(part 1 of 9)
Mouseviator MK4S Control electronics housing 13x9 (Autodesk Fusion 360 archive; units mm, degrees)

design "Mouseviator MK4S Control electronics housing 13x9" references "aurdino UNO v5"
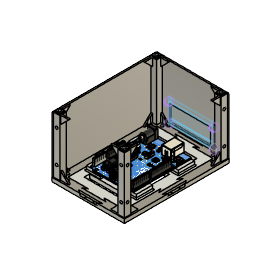
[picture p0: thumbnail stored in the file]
part number: Mouseviator MK4S Control electronics housing 13x9
parameter "plate_width" = 130
parameter "plate_height" = 90
parameter "join_width1" = 10
parameter "join_width2" = 15
parameter "join_depth" = 3
parameter "plate_thick" = 5
parameter "plate_mount_square_side" = 7
parameter "locke_handle_height_1" = 8
parameter "lock_handle_chamfer_1" = 5
parameter "lock_handle_fillet_1" = 0.5
parameter "column_height" = 70
parameter "support_column_side" = 8
parameter "top_cover_thickness" = 3
parameter "wall_clearance" = 0.05
parameter "print_layer_height" = 0.2
parameter "side_wall_thick1" = 0.95 (= "( ( plate_square_thick - support_column_side ) / 2 ) - wall_clearance")
parameter "side_wall_thick2" = 1.95 (= "plate_square_thick - support_column_side - wall_clearance")
parameter "side_wall_length_L_inner" = 111.9 (= "plate_width - ( side_wall_col_length * 2 )")
parameter "side_wall_length_S_inner" = 71.9 (= "plate_height - ( side_wall_col_length * 2 )")
parameter "join_key_d" = 1.5 (= "join_depth / 2")
parameter "join_key_distance" = 5 (= "join_width1 / 2")
parameter "locke_handle_height_2" = 8
parameter "lock_handle_chamfer_2" = 5
parameter "lock_handle_fillet_2" = 0.5
parameter "locke_handle_height_3" = 8
parameter "lock_handle_chamfer_3" = 5
parameter "lock_handle_fillet_3" = 0.5
parameter "lock_column_clearance" = 0.075 (= "wall_clearance * 1.5")
parameter "wago_heigh" = 18
parameter "wago_width" = 6
parameter "wago5_width" = 30 (= "5 * wago_width")
parameter "wago_depth" = 8
parameter "wago10_box_width" = 64 (= "( wago5_width * 2 ) + ( 2 * 2.00 mm )")
parameter "wago_box_height" = 12 (= "wago_depth + ( 2 * 2.00 mm )")
parameter "wago5_box_width" = 34 (= "( wago_width * 5 ) + ( 2 * 2.00 mm )")
parameter "wago3_box_width" = 22.6 (= "wago_width * 3.1 + ( 2 * 2.00 mm )")
parameter "wago_wall_thick" = 2
parameter "mosfet_board_width" = 32.5
parameter "mosfet_baord_height" = 16.5
parameter "fan_relay_board_width" = 33
parameter "fan_relay_board_height" = 25
parameter "uno_doors_clearance" = 0.1
parameter "uno_doors_thick" = 2
parameter "plate_height_1" = 90
parameter "join_width1_1" = 10
parameter "join_width2_1" = 15
parameter "join_depth_1" = 3
parameter "column_height_1" = 70
parameter "support_column_side_1" = 8
parameter "wall_clearance_1" = 0.05
parameter "side_wall_thick1_1" = 0.95 (= "( ( plate_square_thick_1 - support_column_side_1 ) / 2 ) - wall_clearance_1")
parameter "side_wall_thick2_1" = 1.95 (= "plate_square_thick_1 - support_column_side_1 - wall_clearance_1")
parameter "plate_height_2" = 90
parameter "join_width1_2" = 10
parameter "join_width2_2" = 15
parameter "join_depth_2" = 3
parameter "column_height_2" = 70
parameter "support_column_side_2" = 8
parameter "wall_clearance_2" = 0.05
parameter "side_wall_thick1_2" = 0.95 (= "( ( plate_square_thick_2 - support_column_side_2 ) / 2 ) - wall_clearance_2")
parameter "side_wall_thick2_2" = 1.95 (= "plate_square_thick_2 - support_column_side_2 - wall_clearance_2")
parameter "plate_height_3" = 90
parameter "join_width1_3" = 10
parameter "join_width2_3" = 15
parameter "join_depth_3" = 3
parameter "column_height_3" = 70
parameter "support_column_side_3" = 8
parameter "wall_clearance_3" = 0.05
parameter "side_wall_thick1_3" = 0.95 (= "( ( plate_square_thick_3 - support_column_side_3 ) / 2 ) - wall_clearance_3")
parameter "side_wall_thick2_3" = 1.95 (= "plate_square_thick_3 - support_column_side_3 - wall_clearance_3")
parameter "uno_doors_clearance_1" = 0.1
parameter "uno_doors_thick_1" = 2
parameter "plate_height_4" = 90
parameter "join_width1_4" = 10
parameter "join_width2_4" = 15
parameter "join_depth_4" = 3
parameter "column_height_4" = 70
parameter "support_column_side_4" = 8
parameter "wall_clearance_4" = 0.05
parameter "side_wall_thick1_4" = 0.95 (= "( ( plate_square_thick_4 - support_column_side_4 ) / 2 ) - wall_clearance_4")
parameter "side_wall_thick2_4" = 1.95 (= "plate_square_thick_4 - support_column_side_4 - wall_clearance_4")
parameter "joiner_spacing_1" = -0.05
parameter "joiner_spacing_2" = -0.05
parameter "joiner_spacing_2_1" = -0.05
parameter "joiner_spacing_2_2" = -0.05
parameter "joiner_spacing_3_1" = -0.05
parameter "base_vertical_support_width" = 8
parameter "plate_square_thick_1" = 10
parameter "wall_rorner_angle_4" = 45
parameter "plate_square_thick_2" = 10
parameter "wall_rorner_angle_5" = 45
parameter "plate_square_thick_3" = 10
parameter "wall_rorner_angle_6" = 45
parameter "plate_square_thick_4" = 10
parameter "wall_rorner_angle_7" = 45
sketch "Sketch1" plane through (0, 0, 0) normal (0, 0, 1) x axis (1, 0, 0)
  line L1 (100.9644, 61.9879) -> (10.9644, 61.9879)
  line L2 (100.9644, -68.0121) -> (100.9644, 61.9879)
  line L3 (10.9644, -68.0121) -> (100.9644, -68.0121)
  line L4 (10.9644, 61.9879) -> (10.9644, -68.0121)
  line L5 (55.9644, -84.5025) -> (55.9644, 72)
  line L6 (146.0369, -3.0121) -> (3.7538, -3.0121)
  line L7 (90.9644, 51.9879) -> (20.9644, 51.9879)
  line L8 (90.9644, -58.0121) -> (90.9644, 51.9879)
  line L9 (20.9644, -58.0121) -> (90.9644, -58.0121)
  line L10 (20.9644, 51.9879) -> (20.9644, -58.0121)
  line L11 (20.9644, 61.9879) -> (10.9644, 61.9879)
  line L12 (20.9644, 51.9879) -> (20.9644, 61.9879)
  line L13 (10.9644, 51.9879) -> (20.9644, 51.9879)
  line L14 (10.9644, 61.9879) -> (10.9644, 51.9879)
  line L15 (90.9644, 61.9879) -> (100.9644, 61.9879)
  line L16 (90.9644, 51.9879) -> (90.9644, 61.9879)
  line L17 (100.9644, 51.9879) -> (90.9644, 51.9879)
  line L18 (100.9644, 61.9879) -> (100.9644, 51.9879)
  line L19 (90.9644, -68.0121) -> (100.9644, -68.0121)
  line L20 (90.9644, -58.0121) -> (90.9644, -68.0121)
  line L21 (100.9644, -58.0121) -> (90.9644, -58.0121)
  line L22 (100.9644, -68.0121) -> (100.9644, -58.0121)
  line L23 (20.9644, -68.0121) -> (10.9644, -68.0121)
  line L24 (20.9644, -58.0121) -> (20.9644, -68.0121)
  line L25 (10.9644, -58.0121) -> (20.9644, -58.0121)
  line L26 (10.9644, -68.0121) -> (10.9644, -58.0121)
  line L27 (92.9644, 59.9879) -> (98.9644, 59.9879)
  line L28 (92.9644, 53.9879) -> (92.9644, 59.9879)
  line L29 (98.9644, 53.9879) -> (92.9644, 53.9879)
  line L30 (98.9644, 59.9879) -> (98.9644, 53.9879)
  line L31 (18.9644, -66.0121) -> (12.9644, -66.0121)
  line L32 (18.9644, -60.0121) -> (18.9644, -66.0121)
  line L33 (12.9644, -60.0121) -> (18.9644, -60.0121)
  line L34 (12.9644, -66.0121) -> (12.9644, -60.0121)
  line L35 (18.9644, 59.9879) -> (12.9644, 59.9879)
  line L36 (18.9644, 53.9879) -> (18.9644, 59.9879)
  line L37 (12.9644, 53.9879) -> (18.9644, 53.9879)
  line L38 (12.9644, 59.9879) -> (12.9644, 53.9879)
  line L39 (92.9644, -66.0121) -> (98.9644, -66.0121)
  line L40 (92.9644, -60.0121) -> (92.9644, -66.0121)
  line L41 (98.9644, -60.0121) -> (92.9644, -60.0121)
  line L42 (98.9644, -66.0121) -> (98.9644, -60.0121)
  line L43 (45.9644, 51.9879) -> (55.9644, 51.9879)
  line L44 (65.9644, 51.9879) -> (55.9644, 51.9879)
  line L45 (55.9644, 54.9879) -> (55.9644, 51.9879)
  line L46 (70.9644, 54.9879) -> (55.9644, 54.9879)
  line L47 (40.9644, 54.9879) -> (55.9644, 54.9879)
  line L48 (40.9644, 54.9879) -> (45.9644, 51.9879)
  line L49 (65.9644, 51.9879) -> (70.9644, 54.9879)
  line L50 (111.4916, 56.9879) -> (2, 56.9879)
  line L51 (40.9644, 58.9879) -> (55.9644, 58.9879)
  line L52 (40.9644, 58.9879) -> (45.9644, 61.9879)
  line L53 (45.9644, 61.9879) -> (55.9644, 61.9879)
  line L54 (65.9644, 61.9879) -> (70.9644, 58.9879)
  line L55 (65.9644, 61.9879) -> (55.9644, 61.9879)
  line L56 (70.9644, 58.9879) -> (55.9644, 58.9879)
  line L57 (70.9644, -61.0121) -> (55.9644, -61.0121)
  line L58 (65.9644, -58.0121) -> (70.9644, -61.0121)
  line L59 (65.9644, -58.0121) -> (55.9644, -58.0121)
  line L60 (40.9644, -61.0121) -> (45.9644, -58.0121)
  line L61 (45.9644, -58.0121) -> (55.9644, -58.0121)
  line L62 (40.9644, -61.0121) -> (55.9644, -61.0121)
  line L63 (40.9644, -65.0121) -> (45.9644, -68.0121)
  line L64 (45.9644, -68.0121) -> (55.9644, -68.0121)
  line L65 (65.9644, -68.0121) -> (55.9644, -68.0121)
  line L66 (65.9644, -68.0121) -> (70.9644, -65.0121)
  line L67 (70.9644, -65.0121) -> (55.9644, -65.0121)
  line L68 (40.9644, -65.0121) -> (55.9644, -65.0121)
  line L69 (45.9644, 51.9879) -> (20.9644, 51.9879)
  line L70 (65.9644, 51.9879) -> (90.9644, 51.9879)
  line L71 (65.9644, -58.0121) -> (90.9644, -58.0121)
  line L72 (45.9644, -58.0121) -> (20.9644, -58.0121)
  line L73 (95.9644, -76) -> (95.9644, 65)
  line L74 (90.9644, 6.9879) -> (90.9644, -3.0121)
  line L75 (90.9644, -13.0121) -> (90.9644, -3.0121)
  line L76 (93.9644, -3.0121) -> (90.9644, -3.0121)
  line L77 (93.9644, 11.9879) -> (93.9644, -3.0121)
  line L78 (93.9644, -18.0121) -> (93.9644, -3.0121)
  line L79 (93.9644, 11.9879) -> (90.9644, 6.9879)
  line L80 (93.9644, -18.0121) -> (90.9644, -13.0121)
  line L81 (97.9644, -18.0121) -> (97.9644, -3.0121)
  line L82 (97.9644, -18.0121) -> (100.9644, -13.0121)
  line L83 (100.9644, -13.0121) -> (100.9644, -3.0121)
  line L84 (97.9644, 11.9879) -> (100.9644, 6.9879)
  line L85 (100.9644, 6.9879) -> (100.9644, -3.0121)
  line L86 (97.9644, 11.9879) -> (97.9644, -3.0121)
  line L87 (13.9644, 11.9879) -> (13.9644, -3.0121)
  line L88 (13.9644, -18.0121) -> (13.9644, -3.0121)
  line L89 (13.9644, -18.0121) -> (10.9644, -13.0121)
  line L90 (10.9644, -13.0121) -> (10.9644, -3.0121)
  line L91 (10.9644, 6.9879) -> (10.9644, -3.0121)
  line L92 (13.9644, 11.9879) -> (10.9644, 6.9879)
  line L93 (17.9644, 11.9879) -> (20.9644, 6.9879)
  line L94 (20.9644, 6.9879) -> (20.9644, -3.0121)
  line L95 (17.9644, 11.9879) -> (17.9644, -3.0121)
  line L96 (17.9644, -18.0121) -> (20.9644, -13.0121)
  line L97 (20.9644, -13.0121) -> (20.9644, -3.0121)
  line L98 (17.9644, -18.0121) -> (17.9644, -3.0121)
  line L99 (90.9644, 6.9879) -> (90.9644, 51.9879)
  line L100 (90.9644, -58.0121) -> (90.9644, -13.0121)
  line L101 (20.9644, -13.0121) -> (20.9644, -58.0121)
  line L102 (20.9644, 6.9879) -> (20.9644, 51.9879)
  line L103 (27.9644, 51.9879) -> (20.9644, 58.9879)
  line L104 (20.9644, 51.9879) -> (27.9644, 58.9879)
  line L105 (27.9644, 58.9879) -> (20.9644, 58.9879)
  line L106 (27.9644, 51.9879) -> (27.9644, 58.9879)
  line L107 (20.9644, 51.9879) -> (27.9644, 51.9879)
  line L108 (20.9644, 58.9879) -> (20.9644, 51.9879)
  line L109 (13.9644, 51.9879) -> (20.9644, 51.9879)
  line L110 (13.9644, 44.9879) -> (13.9644, 51.9879)
  line L111 (20.9644, 44.9879) -> (13.9644, 44.9879)
  line L112 (20.9644, 51.9879) -> (20.9644, 44.9879)
  line L113 (20.9644, 44.9879) -> (13.9644, 51.9879)
  line L114 (20.9644, 51.9879) -> (13.9644, 44.9879)
  line L115 (75, 60.4879) -> (35.7947, 60.4879)
  line L116 (12.4644, -21) -> (12.4644, 12.5586)
  line L117 (15.9644, -29) -> (15.9644, 22)
  circle C1 centre (24.4644, 55.4879) radius 1.5
  circle C2 centre (87.4644, 55.4879) radius 1.5
  circle C3 centre (24.4644, -61.5121) radius 1.5
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  point P38 (55.9644, 51.9879)
  point P49 (55.9644, 61.9879)
  point P39 (45.9644, 51.9879)
  point P48 (45.9644, 61.9879)
  point P40 (65.9644, 51.9879)
  point P51 (65.9644, 61.9879)
  point P41 (55.9644, 54.9879)
  point P46 (55.9644, 58.9879)
  point P42 (70.9644, 54.9879)
  point P50 (70.9644, 58.9879)
  point P43 (40.9644, 54.9879)
  point P47 (40.9644, 58.9879)
  point P55 (55.9644, -58.0121)
  point P56 (45.9644, -58.0121)
  point P54 (65.9644, -58.0121)
  point P52 (55.9644, -61.0121)
  point P53 (70.9644, -61.0121)
  point P57 (40.9644, -61.0121)
  point P63 (55.9644, -65.0121)
  point P59 (40.9644, -65.0121)
  point P58 (45.9644, -68.0121)
  point P60 (55.9644, -68.0121)
  point P62 (70.9644, -65.0121)
  point P61 (65.9644, -68.0121)
  point P66 (90.9644, -3.0121)
  point P75 (100.9644, -3.0121)
  point P67 (90.9644, 6.9879)
  point P76 (100.9644, 6.9879)
  point P68 (90.9644, -13.0121)
  point P74 (100.9644, -13.0121)
  point P69 (93.9644, -3.0121)
  point P72 (97.9644, -3.0121)
  point P70 (93.9644, 11.9879)
  point P77 (97.9644, 11.9879)
  point P71 (93.9644, -18.0121)
  point P73 (97.9644, -18.0121)
  point P86 (20.9644, -3.0121)
  point P84 (20.9644, 6.9879)
  point P88 (20.9644, -13.0121)
  point P87 (17.9644, -3.0121)
  point P85 (17.9644, 11.9879)
  point P89 (17.9644, -18.0121)
  point P78 (13.9644, -3.0121)
  point P80 (13.9644, -18.0121)
  point P81 (10.9644, -13.0121)
  point P82 (10.9644, -3.0121)
  point P83 (10.9644, 6.9879)
  point P79 (13.9644, 11.9879)
  point P93 (24.4644, 55.4879)
  point P102 (17.4644, 48.4879)
  point P108 (50.9644, 60.4879)
  point P118 (12.4644, 1.9879)
  point P2 (10.9644, 61.9879)
  point P3 (100.9644, 61.9879)
  point P5 (10.9644, -68.0121)
  point P95 (20.9644, 51.9879)
  point P99 (13.9644, 51.9879)
  point P101 (20.9644, 44.9879)
  horizontal L1
  vertical L2
  horizontal L3
  vertical L4
  perpendicular L3 L5
  horizontal L6
  horizontal L11
  vertical L12
  horizontal L13
  vertical L14
  horizontal L15
  vertical L16
  horizontal L17
  vertical L18
  horizontal L19
  vertical L20
  horizontal L21
  vertical L22
  horizontal L23
  vertical L24
  horizontal L25
  vertical L26
  midpoint L7 P38
  perpendicular L8 L43
  perpendicular L5 L44
  perpendicular L44 L45
  perpendicular L45 L46
  perpendicular L45 L47
  parallel L1 L50
  symmetric P38 L50 P49
  symmetric P39 L50 P48
  symmetric P40 L50 P51
  symmetric P41 L50 P46
  symmetric P42 L50 P50
  symmetric P43 L50 P47
  symmetric L6 P38 P55
  symmetric L6 P39 P56
  symmetric L6 P40 P54
  symmetric L6 P41 P52
  symmetric L6 P42 P53
  symmetric L6 P43 P57
  symmetric L6 P46 P63
  symmetric L6 P47 P59
  symmetric L6 P48 P58
  symmetric L6 P49 P60
  symmetric L6 P50 P62
  symmetric L6 P51 P61
  parallel L8 L73
  midpoint L8 P66
  perpendicular L6 L74
  perpendicular L6 L75
  perpendicular L74 L76
  perpendicular L76 L77
  perpendicular L76 L78
  symmetric L73 P66 P75
  symmetric L73 P67 P76
  symmetric L73 P68 P74
  symmetric L73 P69 P72
  symmetric L73 P70 P77
  symmetric L73 P71 P73
  symmetric L5 P66 P86
  symmetric L5 P67 P84
  symmetric L5 P68 P88
  symmetric L5 P69 P87
  symmetric L5 P70 P85
  symmetric L5 P71 P89
  symmetric L5 P72 P78
  symmetric L5 P73 P80
  symmetric L5 P74 P81
  symmetric L5 P75 P82
  symmetric L5 P76 P83
  symmetric L5 P77 P79
  midpoint L104 P93
  horizontal L105
  vertical L106
  horizontal L107
  vertical L108
  horizontal L109
  vertical L110
  horizontal L111
  vertical L112
  perpendicular L113 L114
  midpoint L114 P102
  perpendicular L5 L115
  coincident L115 P108
  parallel L4 L116
  coincident L116 P118
  parallel L116 L117
  dimension "d7" distance P2 P3 = 90 (= "plate_height")
  dimension "d8" distance P2 P5 = 130 (= "plate_width")
  dimension "d9" distance L4 L5 = 45 (= "plate_height / 2")
  dimension "d10" distance L1 L6 = 65 (= "plate_width / 2")
  dimension "plate_square_thick" = 10
  dimension "column_lock_spacing" = 2
  dimension "d14" distance P38 P39 = 10 (= "join_width1")
  dimension "d15" distance P38 P40 = 10 (= "join_width1")
  dimension "d16" distance P38 P41 = 3 (= "join_depth")
  dimension "d17" distance P41 P42 = 15 (= "join_width2")
  dimension "d18" distance P41 P43 = 15 (= "join_width2")
  dimension "d19" distance L1 L50 = 5 (= "plate_square_thick / 2")
  dimension "d20" distance L2 L73 = 5 (= "plate_square_thick / 2")
  dimension "d21" distance P66 P67 = 10 (= "join_width1")
  dimension "d22" distance P66 P68 = 10 (= "join_width1")
  dimension "d23" distance P66 P69 = 3
  dimension "d24" distance P69 P70 = 15 (= "join_width2")
  dimension "d25" distance P69 P71 = 15 (= "join_width2")
  dimension "plate_mount_hole_d" diameter C1 = 3
  dimension "d34" distance P95 P99 = 7 (= "plate_mount_square_side")
  dimension "d35" distance P95 P101 = 7 (= "plate_mount_square_side")
  dimension "d36" diameter = 3
  dimension "d245" distance L1 L115 = 1.5 (= "join_depth / 2")
  dimension "d246" diameter = 1.5 (= "join_key_d")
  dimension "d248" distance L5 P108 = 5 (= "join_key_distance")
  dimension "d250" distance L4 L116 = 1.5 (= "join_depth / 2")
  dimension "d251" diameter = 1.5
  dimension "d252" distance L6 P118 = 5 (= "join_key_distance")
  dimension "d253" distance L4 L117 = 5 (= "plate_square_thick / 2")
  dimension "d32" R-Pattern1-uDistance = 63 (= "plate_height - ( plate_square_thick * 2 ) - plate_mount_square_side")
  dimension "d33" R-Pattern1-vDistance = -117 (= "-( plate_width - ( plate_square_thick * 2 ) + ( plate_mount_square_side ) )")
  dimension "d39" R-Pattern2-uDistance = 76.5 (= "plate_height - plate_square_thick - ( plate_mount_square_side / 2 )")
  dimension "d40" R-Pattern2-vDistance = -103 (= "-( plate_width - ( plate_square_thick * 2 ) - plate_mount_square_side )")
  dimension "lock_handle_hole_d_1" diameter = 5
  dimension "lock_handle_hole_d_2" diameter = 5
  dimension "lock_handle_hole_d_2_1" diameter = 5
  dimension "lock_handle_hole_d_2_2" diameter = 5
  dimension "lock_handle_hole_d_3" diameter = 5
  dimension "cable_hole_d_1_2" diameter = 10
extrude "Extrude1" new body sketch "Sketch1" along normal blind 5 (= "plate_thick")
sketch "Sketch2" plane through (0, 0, 5) normal (0, 0, 1) x axis (-1, 0, 0)
  line L1 (-98.9644, -53.9879) -> (-98.9644, -59.9879)
  line L2 (-92.9644, -53.9879) -> (-98.9644, -53.9879)
  line L3 (-92.9644, -59.9879) -> (-92.9644, -53.9879)
  line L4 (-98.9644, -59.9879) -> (-92.9644, -59.9879)
  line L5 (-12.9644, 60.0121) -> (-12.9644, 66.0121)
  line L6 (-18.9644, 60.0121) -> (-12.9644, 60.0121)
  line L7 (-18.9644, 66.0121) -> (-18.9644, 60.0121)
  line L8 (-12.9644, 66.0121) -> (-18.9644, 66.0121)
  line L9 (-45.9644, -51.9879) -> (-20.9644, -51.9879)
  line L10 (-40.9644, -54.9879) -> (-45.9644, -51.9879)
  line L11 (-70.9644, -54.9879) -> (-40.9644, -54.9879)
  line L12 (-65.9644, -51.9879) -> (-70.9644, -54.9879)
  line L13 (-90.9644, -51.9879) -> (-65.9644, -51.9879)
  line L14 (-90.9644, -6.9879) -> (-90.9644, -51.9879)
  line L15 (-93.9644, -11.9879) -> (-90.9644, -6.9879)
  line L16 (-93.9644, 18.0121) -> (-93.9644, -11.9879)
  line L17 (-90.9644, 13.0121) -> (-93.9644, 18.0121)
  line L18 (-90.9644, 58.0121) -> (-90.9644, 13.0121)
  line L19 (-65.9644, 58.0121) -> (-90.9644, 58.0121)
  line L20 (-70.9644, 61.0121) -> (-65.9644, 58.0121)
  line L21 (-40.9644, 61.0121) -> (-70.9644, 61.0121)
  line L22 (-45.9644, 58.0121) -> (-40.9644, 61.0121)
  line L23 (-20.9644, 58.0121) -> (-45.9644, 58.0121)
  line L24 (-20.9644, 13.0121) -> (-20.9644, 58.0121)
  line L25 (-17.9644, 18.0121) -> (-20.9644, 13.0121)
  line L26 (-17.9644, -11.9879) -> (-17.9644, 18.0121)
  line L27 (-20.9644, -6.9879) -> (-17.9644, -11.9879)
  line L28 (-20.9644, -51.9879) -> (-20.9644, -6.9879)
  line L29 (-12.9644, -53.9879) -> (-18.9644, -53.9879)
  line L30 (-12.9644, -59.9879) -> (-12.9644, -53.9879)
  line L31 (-18.9644, -59.9879) -> (-12.9644, -59.9879)
  line L32 (-18.9644, -53.9879) -> (-18.9644, -59.9879)
  line L33 (-98.9644, 60.0121) -> (-92.9644, 60.0121)
  line L34 (-98.9644, 66.0121) -> (-98.9644, 60.0121)
  line L35 (-92.9644, 66.0121) -> (-98.9644, 66.0121)
  line L36 (-92.9644, 60.0121) -> (-92.9644, 66.0121)
  line L37 (-10.9644, -6.9879) -> (-10.9644, -61.9879)
  line L38 (-13.9644, -11.9879) -> (-10.9644, -6.9879)
  line L39 (-13.9644, 18.0121) -> (-13.9644, -11.9879)
  line L40 (-10.9644, 13.0121) -> (-13.9644, 18.0121)
  line L41 (-10.9644, 68.0121) -> (-10.9644, 13.0121)
  line L42 (-45.9644, 68.0121) -> (-10.9644, 68.0121)
  line L43 (-40.9644, 65.0121) -> (-45.9644, 68.0121)
  line L44 (-70.9644, 65.0121) -> (-40.9644, 65.0121)
  line L45 (-65.9644, 68.0121) -> (-70.9644, 65.0121)
  line L46 (-100.9644, 68.0121) -> (-65.9644, 68.0121)
  line L47 (-100.9644, 13.0121) -> (-100.9644, 68.0121)
  line L48 (-97.9644, 18.0121) -> (-100.9644, 13.0121)
  line L49 (-97.9644, -11.9879) -> (-97.9644, 18.0121)
  line L50 (-100.9644, -6.9879) -> (-97.9644, -11.9879)
  line L51 (-100.9644, -61.9879) -> (-100.9644, -6.9879)
  line L52 (-65.9644, -61.9879) -> (-100.9644, -61.9879)
  line L53 (-70.9644, -58.9879) -> (-65.9644, -61.9879)
  line L54 (-40.9644, -58.9879) -> (-70.9644, -58.9879)
  line L55 (-45.9644, -61.9879) -> (-40.9644, -58.9879)
  line L56 (-10.9644, -61.9879) -> (-45.9644, -61.9879)
  circle C1 centre (-17.4644, -48.4879) radius 1.5
  circle C2 centre (-93.9644, -48.4879) radius 1.5
  circle C3 centre (-87.4644, -55.4879) radius 1.5
  circle C4 centre (-24.4644, -55.4879) radius 1.5
  circle C5 centre (-24.4644, 61.5121) radius 1.5
  circle C6 centre (-17.4644, 54.5121) radius 1.5
  circle C7 centre (-93.9644, 54.5121) radius 1.5
  circle C8 centre (-87.4644, 61.5121) radius 1.5
hole "Hole1" HoleDepth 18 HoleDiameter 3.4 TipAngle 118
sketch "Sketch1" plane through (0, 0, 0) normal (0, 0, 1) x axis (1, 0, 0)
  line L1 (-15, -9) -> (-15, 21)
  line L2 (-7, 6) -> (-28, 6)
  line L3 (-18, 16) -> (-18, 6)
  line L4 (-18, -4) -> (-18, 6)
  line L5 (-15, 21) -> (-18, 16)
  line L6 (-15, -9) -> (-18, -4)
  line L7 (-21, -9) -> (-18, -4)
  line L8 (-18, -4) -> (-18, 6)
  line L9 (-18, 16) -> (-18, 6)
  line L10 (-21, 21) -> (-18, 16)
  line L11 (-21, -9) -> (-21, 21)
  line L12 (-15.05, 20.8195) -> (-18, 15.9028)
  line L13 (-15.05, -8.8195) -> (-15.05, 20.8195)
  line L14 (-15.05, -8.8195) -> (-18, -3.9028)
  line L15 (-20.95, -8.8195) -> (-18, -3.9028)
  line L16 (-20.95, -8.8195) -> (-20.95, 20.8195)
  line L17 (-20.95, 20.8195) -> (-18, 15.9028)
  line L18 (-16.5, -15) -> (-16.5, 22.7414)
  circle C1 centre (-16.5, 11) radius 0.75
  circle C2 centre (-16.5, 11) radius 0.675
  circle C3 centre (-16.5, 1) radius 0.675
  circle C4 centre (-19.5, 11) radius 0.675
  circle C5 centre (-19.5, 1) radius 0.675
  point P2 (-15, 21)
  point P13 (-21, 21)
  point P3 (-15, -9)
  point P10 (-21, -9)
  point P6 (-18, 6)
  point P11 (-18, 6)
  point P7 (-18, 16)
  point P12 (-18, 16)
  point P8 (-18, -4)
  point P9 (-18, -4)
  point P22 (-16.5, 11)
  vertical L1
  horizontal L2
  perpendicular L2 L3
  perpendicular L2 L4
  symmetric P2 L3 P13
  symmetric P3 L3 P10
  symmetric P6 L3 P11
  symmetric P7 L3 P12
  symmetric L3 P8 P9
  parallel L1 L18
  coincident L18 P22
  symmetric L2 C2 C3
  symmetric L4 C2 C4
  symmetric L4 C3 C5
  dimension "d49" distance P6 P7 = 10 (= "join_width1")
  dimension "d50" distance P6 P8 = 10 (= "join_width1")
  dimension "d51" distance P2 P3 = 30 (= "join_width2 * 2")
  dimension "d52" distance L1 L3 = 3 (= "join_depth")
  dimension "joiner_spacing" = -0.05
  dimension "d256" distance L9 L18 = 1.5 (= "join_depth / 2")
  dimension "d257" diameter C1 = 1.5 (= "join_key_d")
  dimension "d258" distance L2 P22 = 5 (= "join_key_distance")
extrude "Extrude1" new body sketch "Sketch1" profile of L13 L12 L15 L14 L16 L17 along normal blind 5 (= "plate_thick")
sketch "Sketch2" plane through (0, 0, 5) normal (0, 0, 1) x axis (-1, 0, 0)
  line L1 (18, -15.9028) -> (15.05, -20.8195)
  line L2 (20.95, -20.8195) -> (18, -15.9028)
  line L3 (20.95, 8.8195) -> (20.95, -20.8195)
  line L4 (18, 3.9028) -> (20.95, 8.8195)
  line L5 (15.05, 8.8195) -> (18, 3.9028)
  line L6 (15.05, -20.8195) -> (15.05, 8.8195)
  line L7 (18, -16) -> (18, -6)
  line L8 (18, 4) -> (18, -6)
  line L9 (17, 3.9028) -> (17, -15.9028)
  line L10 (18, 3.9028) -> (17, 3.9028)
  line L11 (19, 3.9028) -> (19, -15.9028)
  line L12 (18, 3.9028) -> (19, 3.9028)
  line L13 (19, -15.9028) -> (18, -15.9028)
  line L14 (17, -15.9028) -> (18, -15.9028)
  point P6 (18, 3.9028)
  point P14 (18, 3.9028)
  point P3 (18, -15.9028)
  point P15 (18, -15.9028)
  vertical L9
  horizontal L10
  vertical L11
  horizontal L12
  coincident P6 P14
  coincident P3 P15
  perpendicular L11 L13
  perpendicular L9 L14
extrude "Extrude2" add sketch "Sketch2" profile of L1 L2 L4 L5 L7 L8 L9 L10 L11 L12 along normal blind 8 named "locke_handle_height"
chamfer "Chamfer1" distance 5 named "lock_handle_chamfer"
sketch "Sketch3" plane through (-19, 0, 0) normal (-1, 0, 0) x axis (0, -1, 0)
  line L1 (-1.0972, 13) -> (3.9028, 8)
  line L2 (-10.9028, 13) -> (-1.0972, 13)
  line L3 (-15.9028, 8) -> (-10.9028, 13)
  line L4 (-15.9028, 5) -> (-15.9028, 8)
  line L5 (3.9028, 5) -> (-15.9028, 5)
  line L6 (3.9028, 8) -> (3.9028, 5)
  line L7 (-6, 14.247) -> (-6, 5)
  line L8 (4.7349, 8.2) -> (-17.4775, 8.2)
  line L9 (3.9028, 5) -> (-15.9028, 5)
  circle C1 centre (-10, 8.2) radius 2.5
  circle C2 centre (-2, 8.2) radius 2.5
  point P8 (-6, 5)
  point P14 (-10, 8.2)
  midpoint L5 P8
  perpendicular L2 L7
  perpendicular L7 L8
  coincident L8 P14
  symmetric L7 C1 C2
  dimension "d59" distance L8 L9 = 3.2 (= "locke_handle_height * 0.4")
  dimension "lock_handle_hole_d" diameter C1 = 5
  dimension "d61" distance L7 P14 = 4 (= "join_width1 * 0.40")
extrude "Extrude3" cut sketch "Sketch3" profile of C1 C2 no distance stored
fillet "Fillet1" radius 0.5 named "lock_handle_fillet"
fillet "Fillet2" radius 0.5 (= "lock_handle_fillet")
sketch "base" plane through (0, 0, 0) normal (0, 0, 1) x axis (1, 0, 0)
  line L1 (12.9644, 53.9879) -> (18.9644, 53.9879)
  line L2 (12.9644, 59.9879) -> (12.9644, 53.9879)
  line L3 (18.9644, 59.9879) -> (12.9644, 59.9879)
  line L4 (18.9644, 53.9879) -> (18.9644, 59.9879)
  line L5 (13.0144, 54.0379) -> (18.9144, 54.0379)
  line L6 (13.0144, 59.9379) -> (13.0144, 54.0379)
  line L7 (18.9144, 59.9379) -> (13.0144, 59.9379)
  line L8 (18.9144, 54.0379) -> (18.9144, 59.9379)
  line L9 (11.9644, 52.9879) -> (19.9644, 52.9879)
  line L10 (11.9644, 60.9879) -> (11.9644, 52.9879)
  line L11 (19.9644, 60.9879) -> (11.9644, 60.9879)
  line L12 (19.9644, 52.9879) -> (19.9644, 60.9879)
  dimension "d67" = 0.05
  dimension "d68" = -1
extrude "Extrude2" new body sketch "base" profile of L1 L2 L3 L4 L9 L10 L11 L12 blind 70 (= "column_height") from offset 5 (= "plate_thick")
extrude "Extrude3" add sketch "Sketch1" profile of L36 L35 L38 L37 along normal blind 75 (= "plate_thick + column_height")
sketch "supports bottom" plane through (0, 0, 5) normal (0, 0, 1) x axis (-1, 0, 0)
  line L1 (-98.9644, -53.9879) -> (-98.9644, -59.9879)
  line L2 (-92.9644, -53.9879) -> (-98.9644, -53.9879)
  line L3 (-92.9644, -59.9879) -> (-92.9644, -53.9879)
  line L4 (-98.9644, -59.9879) -> (-92.9644, -59.9879)
  line L5 (-12.9644, 60.0121) -> (-12.9644, 66.0121)
  line L6 (-18.9644, 60.0121) -> (-12.9644, 60.0121)
  line L7 (-18.9644, 66.0121) -> (-18.9644, 60.0121)
  line L8 (-12.9644, 66.0121) -> (-18.9644, 66.0121)
  line L9 (-45.9644, -51.9879) -> (-20.9644, -51.9879)
  line L10 (-40.9644, -54.9879) -> (-45.9644, -51.9879)
  line L11 (-70.9644, -54.9879) -> (-40.9644, -54.9879)
  line L12 (-65.9644, -51.9879) -> (-70.9644, -54.9879)
  line L13 (-90.9644, -51.9879) -> (-65.9644, -51.9879)
  line L14 (-90.9644, -6.9879) -> (-90.9644, -51.9879)
  line L15 (-93.9644, -11.9879) -> (-90.9644, -6.9879)
  line L16 (-93.9644, 18.0121) -> (-93.9644, -11.9879)
  line L17 (-90.9644, 13.0121) -> (-93.9644, 18.0121)
  line L18 (-90.9644, 58.0121) -> (-90.9644, 13.0121)
  line L19 (-65.9644, 58.0121) -> (-90.9644, 58.0121)
  line L20 (-70.9644, 61.0121) -> (-65.9644, 58.0121)
  line L21 (-40.9644, 61.0121) -> (-70.9644, 61.0121)
  line L22 (-45.9644, 58.0121) -> (-40.9644, 61.0121)
  line L23 (-20.9644, 58.0121) -> (-45.9644, 58.0121)
  line L24 (-20.9644, 13.0121) -> (-20.9644, 58.0121)
  line L25 (-17.9644, 18.0121) -> (-20.9644, 13.0121)
  line L26 (-17.9644, -11.9879) -> (-17.9644, 18.0121)
  line L27 (-20.9644, -6.9879) -> (-17.9644, -11.9879)
  line L28 (-20.9644, -51.9879) -> (-20.9644, -6.9879)
  line L29 (-12.9644, -53.9879) -> (-18.9644, -53.9879)
  line L30 (-12.9644, -59.9879) -> (-12.9644, -53.9879)
  line L31 (-18.9644, -59.9879) -> (-12.9644, -59.9879)
  line L32 (-18.9644, -53.9879) -> (-18.9644, -59.9879)
  line L33 (-98.9644, 60.0121) -> (-92.9644, 60.0121)
  line L34 (-98.9644, 66.0121) -> (-98.9644, 60.0121)
  line L35 (-92.9644, 66.0121) -> (-98.9644, 66.0121)
  line L36 (-92.9644, 60.0121) -> (-92.9644, 66.0121)
  line L37 (-10.9644, -6.9879) -> (-10.9644, -61.9879)
  line L38 (-13.9644, -11.9879) -> (-10.9644, -6.9879)
  line L39 (-13.9644, 18.0121) -> (-13.9644, -11.9879)
  line L40 (-10.9644, 13.0121) -> (-13.9644, 18.0121)
  line L41 (-10.9644, 68.0121) -> (-10.9644, 13.0121)
  line L42 (-45.9644, 68.0121) -> (-10.9644, 68.0121)
  line L43 (-40.9644, 65.0121) -> (-45.9644, 68.0121)
  line L44 (-70.9644, 65.0121) -> (-40.9644, 65.0121)
  line L45 (-65.9644, 68.0121) -> (-70.9644, 65.0121)
  line L46 (-100.9644, 68.0121) -> (-65.9644, 68.0121)
  line L47 (-100.9644, 13.0121) -> (-100.9644, 68.0121)
  line L48 (-97.9644, 18.0121) -> (-100.9644, 13.0121)
  line L49 (-97.9644, -11.9879) -> (-97.9644, 18.0121)
  line L50 (-100.9644, -6.9879) -> (-97.9644, -11.9879)
  line L51 (-100.9644, -61.9879) -> (-100.9644, -6.9879)
  line L52 (-65.9644, -61.9879) -> (-100.9644, -61.9879)
  line L53 (-70.9644, -58.9879) -> (-65.9644, -61.9879)
  line L54 (-40.9644, -58.9879) -> (-70.9644, -58.9879)
  line L55 (-45.9644, -61.9879) -> (-40.9644, -58.9879)
  line L56 (-10.9644, -61.9879) -> (-45.9644, -61.9879)
  line L57 (-11.9644, -52.9879) -> (-19.9644, -52.9879)
  line L58 (-11.9644, -60.9879) -> (-11.9644, -52.9879)
  line L59 (-19.9644, -60.9879) -> (-11.9644, -60.9879)
  line L60 (-19.9644, -52.9879) -> (-19.9644, -60.9879)
  line L61 (-14.9644, -52.9879) -> (-12.9644, -52.9879)
  line L62 (-14.9644, -42.9879) -> (-14.9644, -52.9879)
  line L63 (-12.9644, -42.9879) -> (-14.9644, -42.9879)
  line L64 (-12.9644, -52.9879) -> (-12.9644, -42.9879)
  line L65 (-29.9644, -59.9879) -> (-19.9644, -59.9879)
  line L66 (-29.9644, -57.9879) -> (-29.9644, -59.9879)
  line L67 (-19.9644, -57.9879) -> (-29.9644, -57.9879)
  line L68 (-19.9644, -59.9879) -> (-19.9644, -57.9879)
  circle C1 centre (-24.4644, 61.5121) radius 1.7
  circle C2 centre (-93.9644, 54.5121) radius 1.7
  circle C3 centre (-87.4644, -55.4879) radius 1.7
  circle C4 centre (-17.4644, -48.4879) radius 1.7
  circle C5 centre (-24.4644, -55.4879) radius 1.7
  circle C6 centre (-93.9644, -48.4879) radius 1.7
  circle C7 centre (-87.4644, 61.5121) radius 1.7
  circle C8 centre (-17.4644, 54.5121) radius 1.7
  circle C9 centre (-17.4644, -48.4879) radius 1.7
  circle C10 centre (-24.4644, -55.4879) radius 1.7
  circle C11 centre (-17.4644, -48.4879) radius 3.15
  circle C12 centre (-24.4644, -55.4879) radius 3.15
  point P70 (-12.9644, -52.9879)
  point P74 (-19.9644, -59.9879)
  point P71 (-14.9644, -52.9879)
  point P73 (-12.9644, -42.9879)
  point P75 (-29.9644, -59.9879)
  point P77 (-19.9644, -57.9879)
  horizontal L61
  vertical L62
  horizontal L63
  vertical L64
  coincident L57 P70
  horizontal L65
  vertical L66
  horizontal L67
  vertical L68
  coincident L60 P74
  concentric C9 C11
  concentric C10 C12
  dimension "column_support_width" distance P70 P71 = 2
  dimension "column_support_height" distance P70 P73 = 10
  dimension "d79" distance P74 P75 = 10 (= "column_support_height")
  dimension "d80" distance P74 P77 = 2 (= "column_support_width")
  dimension "M3_head_d" diameter C11 = 6.3
  dimension "d85" diameter C12 = 6.3 (= "M3_head_d")
extrude "Extrude5" add sketch "supports bottom" profile of L53 L57 L60 L61 L62 L63 L64 L65 L66 L67 L68 C11 C12 along normal blind 10 (= "column_support_height")
chamfer "Chamfer2" distance 10 (= "column_support_height")
sketch "left side holes" plane through (0, 0, 75) normal (0, 0, 1) x axis (-1, 0, 0)
  line L1 (-11.9644, -60.9879) -> (-19.9644, -60.9879)
  line L2 (-11.9644, -52.9879) -> (-11.9644, -60.9879)
  line L3 (-19.9644, -52.9879) -> (-11.9644, -52.9879)
  line L4 (-19.9644, -60.9879) -> (-19.9644, -52.9879)
  line L5 (-19.9644, -57.9879) -> (-29.9644, -57.9879)
  line L6 (-19.9644, -59.9879) -> (-19.9644, -57.9879)
  line L7 (-29.9644, -59.9879) -> (-19.9644, -59.9879)
  line L8 (-29.9644, -57.9879) -> (-29.9644, -59.9879)
  line L9 (-14.9644, -42.9879) -> (-14.9644, -52.9879)
  line L10 (-12.9644, -42.9879) -> (-14.9644, -42.9879)
  line L11 (-14.9644, -52.9879) -> (-12.9644, -52.9879)
  line L12 (-12.9644, -52.9879) -> (-12.9644, -42.9879)
  line L13 (-18.9144, -59.9379) -> (-13.0144, -59.9379)
  line L14 (-18.9144, -54.0379) -> (-18.9144, -59.9379)
  line L15 (-13.0144, -54.0379) -> (-18.9144, -54.0379)
  line L16 (-13.0144, -59.9379) -> (-13.0144, -54.0379)
  line L17 (-18.9644, -59.9879) -> (-12.9644, -59.9879)
  line L18 (-18.9644, -53.9879) -> (-18.9644, -59.9879)
  line L19 (-12.9644, -53.9879) -> (-18.9644, -53.9879)
  line L20 (-12.9644, -59.9879) -> (-12.9644, -53.9879)
  circle C1 centre (-15.9644, -56.9879) radius 1.7
  dimension "M3_d" diameter C1 = 3.4
extrude "Extrude6" add sketch "left side holes" profile of L3 L4 L5 L6 L7 L8 L9 L10 L11 L12 no distance stored
chamfer "Chamfer3" distance 10 (= "column_support_height")
hole "Hole1" HoleDepth 10 (= "column_support_height") HoleDiameter 3.4 TipAngle 118
sketch "Sketch2" plane through (11.9644, 0, 0) normal (-1, 0, 0) x axis (0, -1, 0)
  line L1 (-52.9879, 5) -> (-60.9879, 5)
  line L2 (-52.9879, 75) -> (-52.9879, 5)
  line L3 (-60.9879, 75) -> (-52.9879, 75)
  line L4 (-60.9879, 5) -> (-60.9879, 75)
  line L5 (-44, 60) -> (-67, 60)
  line L6 (-48, 20) -> (-69, 20)
  circle C1 centre (-56.9879, 60) radius 1.7
  circle C2 centre (-56.9879, 20) radius 1.7
  point P14 (-56.9879, 60)
  point P15 (-56.9879, 20)
  point P5 (-60.9879, 75)
  point P2 (-60.9879, 5)
  perpendicular L2 L5
  perpendicular L2 L6
  coincident L5 P14
  coincident L6 P15
  dimension "d96" distance P5 L5 = 15 (= "column_support_height * 1.5")
  dimension "d97" distance P2 L6 = 15 (= "column_support_height * 1.5")
  dimension "d98" diameter C1 = 3.4 (= "M3_d")
  dimension "d100" distance L4 P14 = 4 (= "support_column_side / 2")
  dimension "d101" diameter C2 = 3.4 (= "M3_d")
  dimension "d102" distance L4 P15 = 4 (= "support_column_side / 2")
sketch "Sketch4" plane through (0, 60.9879, 0) normal (0, 1, 0) x axis (-1, 0, 0)
  line L1 (-11.9644, 5) -> (-19.9644, 5)
  line L2 (-11.9644, 75) -> (-11.9644, 5)
  line L3 (-19.9644, 75) -> (-11.9644, 75)
  line L4 (-19.9644, 5) -> (-19.9644, 75)
  line L5 (-23.511, 60) -> (-11.9644, 60)
  line L6 (-25, 20) -> (-11.9644, 20)
  circle C1 centre (-15.9644, 60) radius 1.7
  circle C2 centre (-15.9644, 20) radius 1.7
  point P7 (-11.9644, 60)
  point P8 (-11.9644, 60)
  point P6 (-11.9644, 20)
  point P10 (-11.9644, 20)
  point P12 (-15.9644, 60)
  point P13 (-15.9644, 20)
  coincident P7 P8
  perpendicular L4 L5
  coincident P6 P10
  perpendicular L2 L6
  coincident L5 P12
  coincident L6 P13
  dimension "d103" diameter C1 = 3.4 (= "M3_d")
  dimension "d104" diameter C2 = 3.4 (= "M3_d")
  dimension "d105" distance L2 P12 = 4 (= "support_column_side / 2")
  dimension "d106" distance L2 P13 = 4 (= "support_column_side / 2")
hole "Hole2" HoleDepth 5.76 (= "support_column_side * 0.72") HoleDiameter 3.4 TipAngle 180
hole "Hole3" HoleDepth 5.76 (= "support_column_side * 0.72") HoleDiameter 3.4 TipAngle 180
copy_paste "CopyPaste1"
copy_paste "CopyPaste2"
copy_paste "CopyPaste3"
position "Position2"
sketch "base" plane through (0, 0, 75) normal (0, 0, 1) x axis (-1, 0, 0)
  line L1 (-10.9644, -61.9879) -> (-10.9644, 68.0121)
  line L2 (-100.9644, -61.9879) -> (-10.9644, -61.9879)
  line L3 (-100.9644, 68.0121) -> (-100.9644, -61.9879)
  line L4 (-10.9644, 68.0121) -> (-100.9644, 68.0121)
  line L5 (-20.9644, -51.9879) -> (-20.9644, 58.0121)
  line L6 (-90.9644, -51.9879) -> (-20.9644, -51.9879)
  line L7 (-90.9644, 58.0121) -> (-90.9644, -51.9879)
  line L8 (-20.9644, 58.0121) -> (-90.9644, 58.0121)
  line L9 (-18.9644, -59.9879) -> (-12.9644, -59.9879)
  line L10 (-18.9644, -53.9879) -> (-18.9644, -59.9879)
  line L11 (-12.9644, -59.9879) -> (-12.9644, -53.9879)
  line L12 (-12.9644, -53.9879) -> (-18.9644, -53.9879)
  line L13 (-92.9644, -59.9879) -> (-92.9644, -53.9879)
  line L14 (-98.9644, -59.9879) -> (-92.9644, -59.9879)
  line L15 (-98.9644, -53.9879) -> (-98.9644, -59.9879)
  line L16 (-92.9644, -53.9879) -> (-98.9644, -53.9879)
  line L17 (-12.9644, 60.0121) -> (-12.9644, 66.0121)
  line L18 (-18.9644, 60.0121) -> (-12.9644, 60.0121)
  line L19 (-18.9644, 66.0121) -> (-18.9644, 60.0121)
  line L20 (-12.9644, 66.0121) -> (-18.9644, 66.0121)
  line L21 (-92.9644, 60.0121) -> (-92.9644, 66.0121)
  line L22 (-98.9644, 60.0121) -> (-92.9644, 60.0121)
  line L23 (-98.9644, 66.0121) -> (-98.9644, 60.0121)
  line L24 (-92.9644, 66.0121) -> (-98.9644, 66.0121)
  line L25 (-40.9644, -58.9879) -> (-55.9644, -58.9879)
  line L26 (-40.9644, -58.9879) -> (-45.9644, -61.9879)
  line L27 (-70.9644, -58.9879) -> (-55.9644, -58.9879)
  line L28 (-65.9644, -61.9879) -> (-70.9644, -58.9879)
  line L29 (-13.9644, -11.9879) -> (-10.9644, -6.9879)
  line L30 (-13.9644, -11.9879) -> (-13.9644, 3.0121)
  line L31 (-13.9644, 18.0121) -> (-13.9644, 3.0121)
  line L32 (-13.9644, 18.0121) -> (-10.9644, 13.0121)
  line L33 (-97.9644, -11.9879) -> (-100.9644, -6.9879)
  line L34 (-97.9644, -11.9879) -> (-97.9644, 3.0121)
  line L35 (-97.9644, 18.0121) -> (-97.9644, 3.0121)
  line L36 (-97.9644, 18.0121) -> (-100.9644, 13.0121)
  line L37 (-65.9644, 68.0121) -> (-70.9644, 65.0121)
  line L38 (-70.9644, 65.0121) -> (-55.9644, 65.0121)
  line L39 (-40.9644, 65.0121) -> (-55.9644, 65.0121)
  line L40 (-40.9644, 65.0121) -> (-45.9644, 68.0121)
  circle C1 centre (-60.9644, -60.4879) radius 0.75
  circle C2 centre (-50.9644, -60.4879) radius 0.75
  circle C3 centre (-12.4644, 8.0121) radius 0.75
  circle C4 centre (-12.4644, -1.9879) radius 0.75
  circle C5 centre (-99.4644, -1.9879) radius 0.75
  circle C6 centre (-99.4644, 8.0121) radius 0.75
  circle C7 centre (-60.9644, 66.5121) radius 0.75
  circle C8 centre (-50.9644, 66.5121) radius 0.75
  dimension "d121" = 10 (= "plate_square_thick")
  dimension "d241" R-Pattern1-vDistance = 120 (= "plate_width - plate_square_thick")
extrude "Extrude1" new body sketch "base" profile of L1 L2 L3 L4 along normal blind 3 (= "top_cover_thickness")
sketch "mount holes" plane through (0, 0, 78) normal (0, 0, 1) x axis (-1, 0, 0)
  line L1 (-100.9644, -61.9879) -> (-100.9644, 68.0121)
  line L2 (-10.9644, -61.9879) -> (-100.9644, -61.9879)
  line L3 (-10.9644, 68.0121) -> (-10.9644, -61.9879)
  line L4 (-100.9644, 68.0121) -> (-10.9644, 68.0121)
  circle C1 centre (-15.9644, -56.9879) radius 1.7
  circle C2 centre (-95.9644, -56.9879) radius 1.7
  circle C3 centre (-15.9644, 63.0121) radius 1.7
  circle C4 centre (-95.9644, 63.0121) radius 1.7
  dimension "d163" R-Pattern1-vDistance = 120 (= "plate_width - plate_square_thick")
hole "Hole1" HoleDepth 4 HoleDiameter 3.4 TipAngle 118 CSDiameter 6.3 CSAngle 90
sketch "wall_base" plane through (0, 0, 5) normal (0, 0, 1) x axis (-1, 0, 0)
  line L1 (-98.9644, -53.9879) -> (-98.9644, -59.9879)
  line L2 (-92.9644, -53.9879) -> (-98.9644, -53.9879)
  line L3 (-92.9644, -59.9879) -> (-92.9644, -53.9879)
  line L4 (-98.9644, -59.9879) -> (-92.9644, -59.9879)
  line L5 (-12.9644, 60.0121) -> (-12.9644, 66.0121)
  line L6 (-18.9644, 60.0121) -> (-12.9644, 60.0121)
  line L7 (-18.9644, 66.0121) -> (-18.9644, 60.0121)
  line L8 (-12.9644, 66.0121) -> (-18.9644, 66.0121)
  line L9 (-45.9644, -51.9879) -> (-20.9644, -51.9879)
  line L10 (-40.9644, -54.9879) -> (-45.9644, -51.9879)
  line L11 (-70.9644, -54.9879) -> (-40.9644, -54.9879)
  line L12 (-65.9644, -51.9879) -> (-70.9644, -54.9879)
  line L13 (-90.9644, -51.9879) -> (-65.9644, -51.9879)
  line L14 (-90.9644, -6.9879) -> (-90.9644, -51.9879)
  line L15 (-93.9644, -11.9879) -> (-90.9644, -6.9879)
  line L16 (-93.9644, 18.0121) -> (-93.9644, -11.9879)
  line L17 (-90.9644, 13.0121) -> (-93.9644, 18.0121)
  line L18 (-90.9644, 58.0121) -> (-90.9644, 13.0121)
  line L19 (-65.9644, 58.0121) -> (-90.9644, 58.0121)
  line L20 (-70.9644, 61.0121) -> (-65.9644, 58.0121)
  line L21 (-40.9644, 61.0121) -> (-70.9644, 61.0121)
  line L22 (-45.9644, 58.0121) -> (-40.9644, 61.0121)
  line L23 (-20.9644, 58.0121) -> (-45.9644, 58.0121)
  line L24 (-20.9644, 13.0121) -> (-20.9644, 58.0121)
  line L25 (-17.9644, 18.0121) -> (-20.9644, 13.0121)
  line L26 (-17.9644, -11.9879) -> (-17.9644, 18.0121)
  line L27 (-20.9644, -6.9879) -> (-17.9644, -11.9879)
  line L28 (-20.9644, -51.9879) -> (-20.9644, -6.9879)
  line L29 (-12.9644, -53.9879) -> (-18.9644, -53.9879)
  line L30 (-12.9644, -59.9879) -> (-12.9644, -53.9879)
  line L31 (-18.9644, -59.9879) -> (-12.9644, -59.9879)
  line L32 (-18.9644, -53.9879) -> (-18.9644, -59.9879)
  line L33 (-98.9644, 60.0121) -> (-92.9644, 60.0121)
  line L34 (-98.9644, 66.0121) -> (-98.9644, 60.0121)
  line L35 (-92.9644, 66.0121) -> (-98.9644, 66.0121)
  line L36 (-92.9644, 60.0121) -> (-92.9644, 66.0121)
  line L37 (-10.9644, -6.9879) -> (-10.9644, -61.9879)
  line L38 (-13.9644, -11.9879) -> (-10.9644, -6.9879)
  line L39 (-13.9644, 18.0121) -> (-13.9644, -11.9879)
  line L40 (-10.9644, 13.0121) -> (-13.9644, 18.0121)
  line L41 (-10.9644, 68.0121) -> (-10.9644, 13.0121)
  line L42 (-45.9644, 68.0121) -> (-10.9644, 68.0121)
  line L43 (-40.9644, 65.0121) -> (-45.9644, 68.0121)
  line L44 (-70.9644, 65.0121) -> (-40.9644, 65.0121)
  line L45 (-65.9644, 68.0121) -> (-70.9644, 65.0121)
  line L46 (-100.9644, 68.0121) -> (-65.9644, 68.0121)
  line L47 (-100.9644, 13.0121) -> (-100.9644, 68.0121)
  line L48 (-97.9644, 18.0121) -> (-100.9644, 13.0121)
  line L49 (-97.9644, -11.9879) -> (-97.9644, 18.0121)
  line L50 (-100.9644, -6.9879) -> (-97.9644, -11.9879)
  line L51 (-100.9644, -61.9879) -> (-100.9644, -6.9879)
  line L52 (-65.9644, -61.9879) -> (-100.9644, -61.9879)
  line L53 (-70.9644, -58.9879) -> (-65.9644, -61.9879)
  line L54 (-40.9644, -58.9879) -> (-70.9644, -58.9879)
  line L55 (-45.9644, -61.9879) -> (-40.9644, -58.9879)
  line L56 (-10.9644, -61.9879) -> (-45.9644, -61.9879)
  line L57 (-100.9644, -61.9879) -> (-100.9644, 68.0121)
  line L58 (-100.9644, -61.9172) -> (-100.0144, -60.9672)
  line L59 (-100.0144, -52.9379) -> (-100.0144, -60.9672)
  line L60 (-99.0144, -52.9379) -> (-100.0144, -52.9379)
  line L61 (-99.0144, 58.9451) -> (-99.0144, -52.9379)
  line L62 (-100.0144, 58.9621) -> (-99.0144, 58.9451)
  line L63 (-100.0144, 66.9914) -> (-100.0144, 58.9621)
  line L64 (-100.9644, 67.9414) -> (-100.0144, 66.9914)
  line L65 (-99.9644, -52.9879) -> (-99.9644, -60.9879)
  line L66 (-98.9644, -52.9879) -> (-99.9644, -52.9879)
  line L67 (-98.9644, 58.9942) -> (-98.9644, -52.9879)
  line L68 (-99.9644, 59.0113) -> (-98.9644, 58.9942)
  line L69 (-99.9644, 67.0121) -> (-99.9644, 59.0113)
  line L70 (-100.9644, -61.9879) -> (-99.9644, -60.9879)
  line L71 (-100.9644, 68.0121) -> (-99.9644, 67.0121)
  circle C1 centre (-24.4644, 61.5121) radius 1.7
  circle C2 centre (-93.9644, 54.5121) radius 1.7
  circle C3 centre (-87.4644, -55.4879) radius 1.7
  circle C4 centre (-17.4644, -48.4879) radius 1.7
  circle C5 centre (-24.4644, -55.4879) radius 1.7
  circle C6 centre (-93.9644, -48.4879) radius 1.7
  circle C7 centre (-87.4644, 61.5121) radius 1.7
  circle C8 centre (-17.4644, 54.5121) radius 1.7
  point P69 (-100.9644, 68.0121)
  point P74 (-100.9644, 68.0121)
  point P68 (-100.9644, -61.9879)
  point P75 (-100.9644, -61.9879)
  point P82 (-100.9644, 67.9414)
  point P83 (-100.9644, -61.9172)
  point P90 (-100.9644, -61.9879)
  point P91 (-100.9644, 68.0121)
  point P77 (-100.0144, -52.9379)
  point P80 (-100.0144, 58.9621)
  coincident P69 P74
  coincident P68 P75
  coincident L47 P82
  coincident L51 P83
  coincident P68 P90
  parallel L58 L70
  coincident P69 P91
  dimension "d147" distance L57 L63 = 0.95 (= "side_wall_thick1")
  dimension "d148" distance L57 L61 = 1.95 (= "side_wall_thick2")
  dimension "d151" distance L57 L59 = 0.95 (= "side_wall_thick1")
  dimension "d157" distance L64 L71 = 0.05 (= "wall_clearance")
  dimension "d158" distance L58 L70 = 0.05 (= "wall_clearance")
  dimension "wall_rorner_angle" angle L46 L71 = 45
  dimension "d165" angle L52 L70 = 45 (= "wall_rorner_angle")
  dimension "d170" distance P75 P77 = 9.05
  dimension "d175" distance P74 P80 = 9.05 (= "side_wall_col_length")
extrude "Extrude1" new body sketch "wall_base" profile of L47 L48 L50 L51 L57 L58 L59 L62 L61 L60 L63 L64 blind 69.9 (= "column_height - ( 2 * wall_clearance )") from offset 0.05 (= "wall_clearance") bodies "side cover"
sketch "Sketch3" plane through (100.9644, 0, 0) normal (1, 0, 0) x axis (0, 1, 0)
  line L1 (61.9172, 5.05) -> (-67.9414, 5.05)
  line L2 (61.9172, 74.95) -> (61.9172, 5.05)
  line L3 (-67.9414, 74.95) -> (61.9172, 74.95)
  line L4 (-67.9414, 5.05) -> (-67.9414, 74.95)
  line L5 (61.9172, 74.95) -> (-67.9414, 74.95)
  line L6 (61.9172, 74.95) -> (61.9172, 5.05)
  line L7 (61.9172, 5.05) -> (-67.9414, 5.05)
  line L8 (-67.9414, 74.95) -> (-67.9414, 5.05)
  line L9 (-57.9414, 64.95) -> (51.9172, 64.95)
  line L10 (-57.9414, 15.05) -> (-57.9414, 64.95)
  line L11 (51.9172, 15.05) -> (-57.9414, 15.05)
  line L12 (51.9172, 64.95) -> (51.9172, 15.05)
  circle C1 centre (-62.995, 60) radius 1.7
  circle C2 centre (-62.995, 20) radius 1.7
  circle C3 centre (56.9879, 60) radius 1.7
  circle C4 centre (56.9879, 20) radius 1.7
hole "Hole1" HoleDepth 4 HoleDiameter 3.4 TipAngle 118
work_plane "WorkPlane1"
work_plane "WorkPlane2"
mirror_component "MirrorComponent1"
derived_instance "DerivedInstance1"
joint "Assemble3" alignAngle 0 alignOffsetX 0 alignOffsetY 0 alignOffsetZ 0
joint "Assemble4" alignAngle 0 alignOffsetX 0 alignOffsetY 0 alignOffsetZ 0
joint "Assemble5" alignAngle 90 alignOffsetX 0 alignOffsetY 0 alignOffsetZ 0
joint "Assemble6" alignAngle 0 alignOffsetX 0 alignOffsetY 0 alignOffsetZ 0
